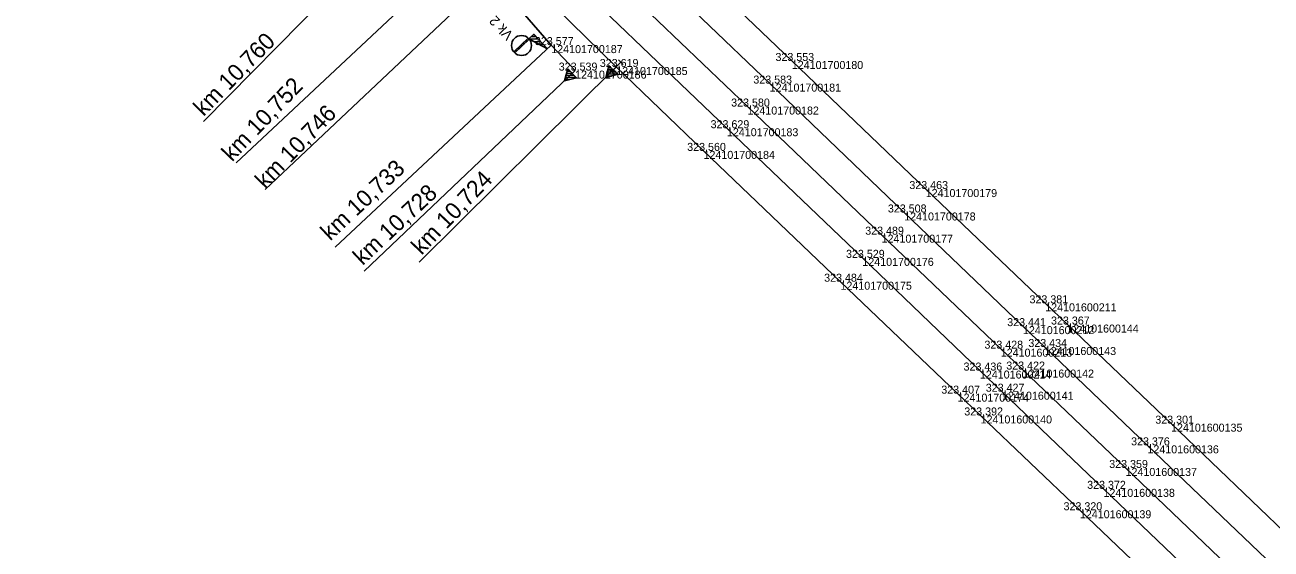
# Model space of a CAD drawing. Extents: x -616949 to -607976, y -1164436 to -1159224.
# Drawn here: x -616541.1 to -616354.1, y -1159570.1 to -1159491.5 of the extents above; entities that cross this region are included whole.
import ezdxf

# ---------------------------------------------------------------- set-up
doc = ezdxf.new("R2010")
doc.units = 0
for name, color, linetype in [('Vrstva 1', 7, 'Continuous'), ('Vrstva 3', 7, 'Continuous'), ('Vrstva 5', 7, 'Continuous'), ('Vrstva 60', 7, 'Continuous'), ('Vrstva 61', 7, 'Continuous')]:
    doc.layers.add(name, color=color, linetype=linetype)

msp = doc.modelspace()

# ---------------------------------------------------------------- linework, layer by layer
at = {"layer": 'Vrstva 1'}
for points in [[(-616354.89, -1159571.54), (-616372.69, -1159554.54), (-616388.1, -1159539.8), (-616391.36, -1159536.67), (-616409.17, -1159519.63), (-616429.35, -1159500.31), (-616459.8, -1159471.15), (-616483.37, -1159448.57), (-616484.54, -1159447.45), (-616487.56, -1159444.55), (-616496.77, -1159435.79), (-616507.3, -1159426.35), (-616520.77, -1159414.64), (-616532.81, -1159403.98), (-616540.16, -1159398.34), (-616541.06, -1159397.62)], [(-616358.37, -1159574.75), (-616375.97, -1159557.93), (-616391.41, -1159543.18), (-616394.69, -1159540.05), (-616412.56, -1159522.96), (-616432.68, -1159503.75), (-616462.85, -1159474.92), (-616479.84, -1159458.67), (-616480.99, -1159457.57), (-616483.82, -1159454.87), (-616498.59, -1159440.73), (-616510.42, -1159429.44), (-616522.43, -1159417.95), (-616529.13, -1159411.54), (-616529.76, -1159410.94)], [(-616329.08, -1159589.6), (-616351, -1159568.64), (-616369.15, -1159551.29), (-616384.7, -1159536.43), (-616388.02, -1159533.25), (-616405.95, -1159516.12), (-616426.03, -1159496.92), (-616456.59, -1159467.68), (-616468.4, -1159456.4), (-616471.42, -1159453.51), (-616478.14, -1159447.08), (-616487.14, -1159438.68), (-616497.27, -1159429.99), (-616507, -1159421.93), (-616516.37, -1159415.51), (-616517.32, -1159414.86)], [(-616360.84, -1159578.72), (-616379.28, -1159561.06), (-616394.48, -1159546.5), (-616397.82, -1159543.33), (-616415.45, -1159526.43), (-616435.76, -1159507), (-616464.71, -1159479.28), (-616465.86, -1159478.17), (-616469.41, -1159474.76), (-616480.17, -1159464.46), (-616487.02, -1159457.86), (-616495.15, -1159449.67), (-616503.93, -1159440.57), (-616510.98, -1159431.67), (-616511.76, -1159430.69)], [(-616458.53, -1159498.36), (-616462.11, -1159494.54), (-616471.35, -1159483.88), (-616480.36, -1159472.39), (-616490.77, -1159457.29), (-616495.92, -1159451.32), (-616496.45, -1159450.7)], [(-616239.15, -1159697.79), (-616239.8, -1159697.28), (-616244.33, -1159693.92), (-616259.78, -1159681.25), (-616268.13, -1159673.95), (-616278.58, -1159664.07), (-616288.41, -1159654.65), (-616299.9, -1159643.65), (-616322.63, -1159621.82), (-616340.65, -1159604.54), (-616363.83, -1159582.4), (-616382.82, -1159564.27), (-616397.71, -1159550.06), (-616401.16, -1159546.79), (-616418.73, -1159530.01), (-616439.27, -1159510.4), (-616452.37, -1159497.82), (-616461.42, -1159488.93), (-616469.22, -1159481.07), (-616478.64, -1159471.37), (-616490.77, -1159457.29), (-616495.92, -1159451.32), (-616496.45, -1159450.7)]]:
    msp.add_lwpolyline(points, dxfattribs=at)
at = {"layer": 'Vrstva 3'}
for p, q in [((-616469.41, -1159474.76), (-616509.38, -1159512.21)), ((-616465.29, -1159478.72), (-616505, -1159516.21)), ((-616465.7, -1159493.93), (-616466, -1159493.92)), ((-616464.04, -1159493.65), (-616465.44, -1159493.6)), ((-616464.41, -1159493.26), (-616465.11, -1159493.24)), ((-616463.68, -1159494.03), (-616464.7, -1159494)), ((-616462.11, -1159494.54), (-616494.51, -1159524.82)), ((-616467.25, -1159495.38), (-616467.54, -1159495.37)), ((-616467.51, -1159495.62), (-616467.54, -1159495.61)), ((-616466.86, -1159495.02), (-616467.16, -1159495.01)), ((-616466.48, -1159494.65), (-616466.77, -1159494.64)), ((-616466.09, -1159494.29), (-616466.38, -1159494.28)), ((-616463.32, -1159494.42), (-616463.96, -1159494.4)), ((-616462.96, -1159494.81), (-616463.23, -1159494.8)), ((-616452.37, -1159497.82), (-616481.9, -1159527.09)), ((-616453.06, -1159498.54), (-616451.68, -1159497.09)), ((-616451.32, -1159497.44), (-616452.04, -1159496.75)), ((-616458.53, -1159498.36), (-616490.17, -1159528.44)), ((-616459.33, -1159499.68), (-616460.08, -1159499.67)), ((-616458.4, -1159499.41), (-616459.99, -1159499.36)), ((-616458.7, -1159499.09), (-616459.91, -1159499.06)), ((-616458.99, -1159498.78), (-616459.81, -1159498.75)), ((-616459.29, -1159498.46), (-616459.71, -1159498.44)), ((-616453.1, -1159499.18), (-616453.85, -1159499.2)), ((-616452.18, -1159498.85), (-616453.78, -1159498.89)), ((-616452.5, -1159498.55), (-616453.71, -1159498.58)), ((-616452.81, -1159498.25), (-616453.63, -1159498.27)), ((-616453.12, -1159497.95), (-616453.55, -1159497.96)), ((-616452.7, -1159498.88), (-616453.43, -1159498.19))]:
    msp.add_line(p, q, dxfattribs=at)
for points in [[(-616467.53, -1159495.63), (-616467.67, -1159495.48), (-616465.62, -1159493.57), (-616465.48, -1159493.72)], [(-616462.7, -1159495.09), (-616464.75, -1159492.9), (-616465.48, -1159493.58)], [(-616453.91, -1159499.42), (-616452.13, -1159498.9), (-616453.47, -1159497.62)], [(-616460.15, -1159499.88), (-616458.35, -1159499.46), (-616459.62, -1159498.11)]]:
    msp.add_lwpolyline(points, close=True, dxfattribs=at)
msp.add_circle((-616466.57, -1159494.6), 1.5, dxfattribs=at)
at = {"layer": 'Vrstva 5'}
msp.add_line((-616482.68, -1159473.97), (-616514.29, -1159505.99), dxfattribs=at)
at = {"layer": 'Vrstva 60'}
for p, q in [((-616462.11, -1159494.54), (-616462.11, -1159494.54)), ((-616452.37, -1159497.82), (-616452.37, -1159497.82)), ((-616426.03, -1159496.92), (-616426.03, -1159496.92)), ((-616458.53, -1159498.36), (-616458.53, -1159498.36)), ((-616429.35, -1159500.31), (-616429.35, -1159500.31)), ((-616432.68, -1159503.75), (-616432.68, -1159503.75)), ((-616435.76, -1159507), (-616435.76, -1159507)), ((-616439.27, -1159510.4), (-616439.27, -1159510.4)), ((-616405.95, -1159516.12), (-616405.95, -1159516.12)), ((-616409.17, -1159519.63), (-616409.17, -1159519.63)), ((-616412.56, -1159522.96), (-616412.56, -1159522.96)), ((-616415.45, -1159526.43), (-616415.45, -1159526.43)), ((-616418.73, -1159530.01), (-616418.73, -1159530.01)), ((-616388.02, -1159533.25), (-616388.02, -1159533.25)), ((-616391.36, -1159536.67), (-616391.36, -1159536.67)), ((-616384.7, -1159536.43), (-616384.7, -1159536.43)), ((-616394.69, -1159540.05), (-616394.69, -1159540.05)), ((-616388.1, -1159539.8), (-616388.1, -1159539.8)), ((-616397.82, -1159543.33), (-616397.82, -1159543.33)), ((-616391.41, -1159543.18), (-616391.41, -1159543.18)), ((-616401.16, -1159546.79), (-616401.16, -1159546.79)), ((-616394.48, -1159546.5), (-616394.48, -1159546.5)), ((-616397.71, -1159550.06), (-616397.71, -1159550.06)), ((-616369.15, -1159551.29), (-616369.15, -1159551.29)), ((-616372.69, -1159554.54), (-616372.69, -1159554.54)), ((-616375.97, -1159557.93), (-616375.97, -1159557.93)), ((-616379.28, -1159561.06), (-616379.28, -1159561.06)), ((-616382.82, -1159564.27), (-616382.82, -1159564.27))]:
    msp.add_line(p, q, dxfattribs=at)

# ---------------------------------------------------------------- texts
at = {"layer": 'Vrstva 3'}
for s, height, rotation, p in [('Vk 2', 1.5, 133.105, (-616467.71, -1159492.94)), ('km 10,752', 2.5, 46.2192, (-616509.99, -1159512.13)), ('km 10,746', 2.5, 46.0628, (-616505, -1159516.21)), ('km 10,733', 2.5, 43.105, (-616495.27, -1159523.98)), ('km 10,724', 2.5, 46.1617, (-616481.56, -1159526.12)), ('km 10,728', 2.5, 43.105, (-616490.42, -1159527.66))]:
    msp.add_text(s, height=height, rotation=rotation, dxfattribs=at).set_placement(p)
at = {"layer": 'Vrstva 5'}
msp.add_text('km 10,760', height=2.5, rotation=45.5819, dxfattribs=at).set_placement((-616514.26, -1159505.33))
at = {"layer": 'Vrstva 60'}
for s, p in [('124101700187', (-616462.11, -1159495.74)), ('124101700185', (-616452.37, -1159499.02)), ('124101700180', (-616426.03, -1159498.12)), ('124101700186', (-616458.53, -1159499.56)), ('124101700181', (-616429.35, -1159501.51)), ('124101700182', (-616432.68, -1159504.95)), ('124101700183', (-616435.76, -1159508.2)), ('124101700184', (-616439.27, -1159511.6)), ('124101700179', (-616405.95, -1159517.32)), ('124101700178', (-616409.17, -1159520.83)), ('124101700177', (-616412.56, -1159524.16)), ('124101700176', (-616415.45, -1159527.63)), ('124101700175', (-616418.73, -1159531.21)), ('124101600211', (-616388.02, -1159534.45)), ('124101600212', (-616391.36, -1159537.87)), ('124101600144', (-616384.7, -1159537.63)), ('124101600213', (-616394.69, -1159541.25)), ('124101600143', (-616388.1, -1159541)), ('124101600214', (-616397.82, -1159544.53)), ('124101600142', (-616391.41, -1159544.38)), ('124101700174', (-616401.16, -1159547.99)), ('124101600141', (-616394.48, -1159547.7)), ('124101600140', (-616397.71, -1159551.26)), ('124101600135', (-616369.15, -1159552.49)), ('124101600136', (-616372.69, -1159555.74)), ('124101600137', (-616375.97, -1159559.13)), ('124101600138', (-616379.28, -1159562.26)), ('124101600139', (-616382.82, -1159565.47))]:
    msp.add_text(s, height=1.2, dxfattribs=at).set_placement(p)
at = {"layer": 'Vrstva 61'}
for s, p in [('323.577', (-616464.56, -1159494.54)), ('323.553', (-616428.48, -1159496.92)), ('323.539', (-616460.99, -1159498.36)), ('323.619', (-616454.83, -1159497.82)), ('323.583', (-616431.8, -1159500.31)), ('323.580', (-616435.13, -1159503.75)), ('323.629', (-616438.21, -1159507)), ('323.560', (-616441.72, -1159510.4)), ('323.463', (-616408.4, -1159516.12)), ('323.508', (-616411.62, -1159519.63)), ('323.489', (-616415.02, -1159522.96)), ('323.529', (-616417.9, -1159526.43)), ('323.484', (-616421.18, -1159530.01)), ('323.381', (-616390.38, -1159533.25)), ('323.367', (-616387.15, -1159536.43)), ('323.441', (-616393.72, -1159536.67)), ('323.428', (-616397.14, -1159540.05)), ('323.434', (-616390.55, -1159539.8)), ('323.436', (-616400.27, -1159543.33)), ('323.422', (-616393.86, -1159543.18)), ('323.407', (-616403.61, -1159546.79)), ('323.427', (-616396.94, -1159546.5)), ('323.392', (-616400.16, -1159550.06)), ('323.301', (-616371.51, -1159551.29)), ('323.376', (-616375.14, -1159554.54)), ('323.359', (-616378.42, -1159557.93)), ('323.372', (-616381.73, -1159561.06)), ('323.320', (-616385.27, -1159564.27))]:
    msp.add_text(s, height=1.2, dxfattribs=at).set_placement(p)

doc.saveas('drawing.dxf')
